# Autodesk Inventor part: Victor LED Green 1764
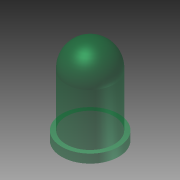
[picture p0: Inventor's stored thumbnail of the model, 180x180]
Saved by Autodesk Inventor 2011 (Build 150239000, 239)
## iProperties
Shininess: 64.0
Length Units: 11272
Angle Units: 11279
Time Units: 11290
Mass Units: 11286
Length Display Precision: 3
Angle Display Precision: 2
Compacted: True
Part Number: Victor LED Green 1764
Document SubType Name: Modeling
Created: 2005-12
Designer: Owner
Material: ABS Plastic
Density: 1 g/cm^3
Density: 0.0
Volumn: 0.0
Area: 0.0
PropertySet Name: Model Information
Control State: 0
Master: False
Checked Out: False
Author: Owner
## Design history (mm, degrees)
sketch "Sketch1"
  geometry: L1 (0, 0)-(0, 9); L2 (-2.491, 6.277)-(-2.491, 0.9); L3 (-2.491, 0.9)-(-2.95, 0.9); L4 (-2.95, 0.9)-(-2.95, 0); L5 (-2.95, 0)-(0, 0); A1 r 2.5 centre (-0.001, 6.5) between (0, 9) and (-2.491, 6.277)
  constraints: 10 end point, 3 parallel, 2 point on circle, 1 centre point, 1 perpendicular, 1 vertical, 1 other
  dimensions: "d0" = 5 diameter of A1; "d1" = 9 distance of L1.start L1.end; "d2" = 0.9 distance of L3.end L4.end; "d3" = 2.95 distance of L4.end L1.start
revolve "Revolution1" sketch "Sketch1" stored, may be unused: angle "d4" = 90 deg
body "Solid1"
